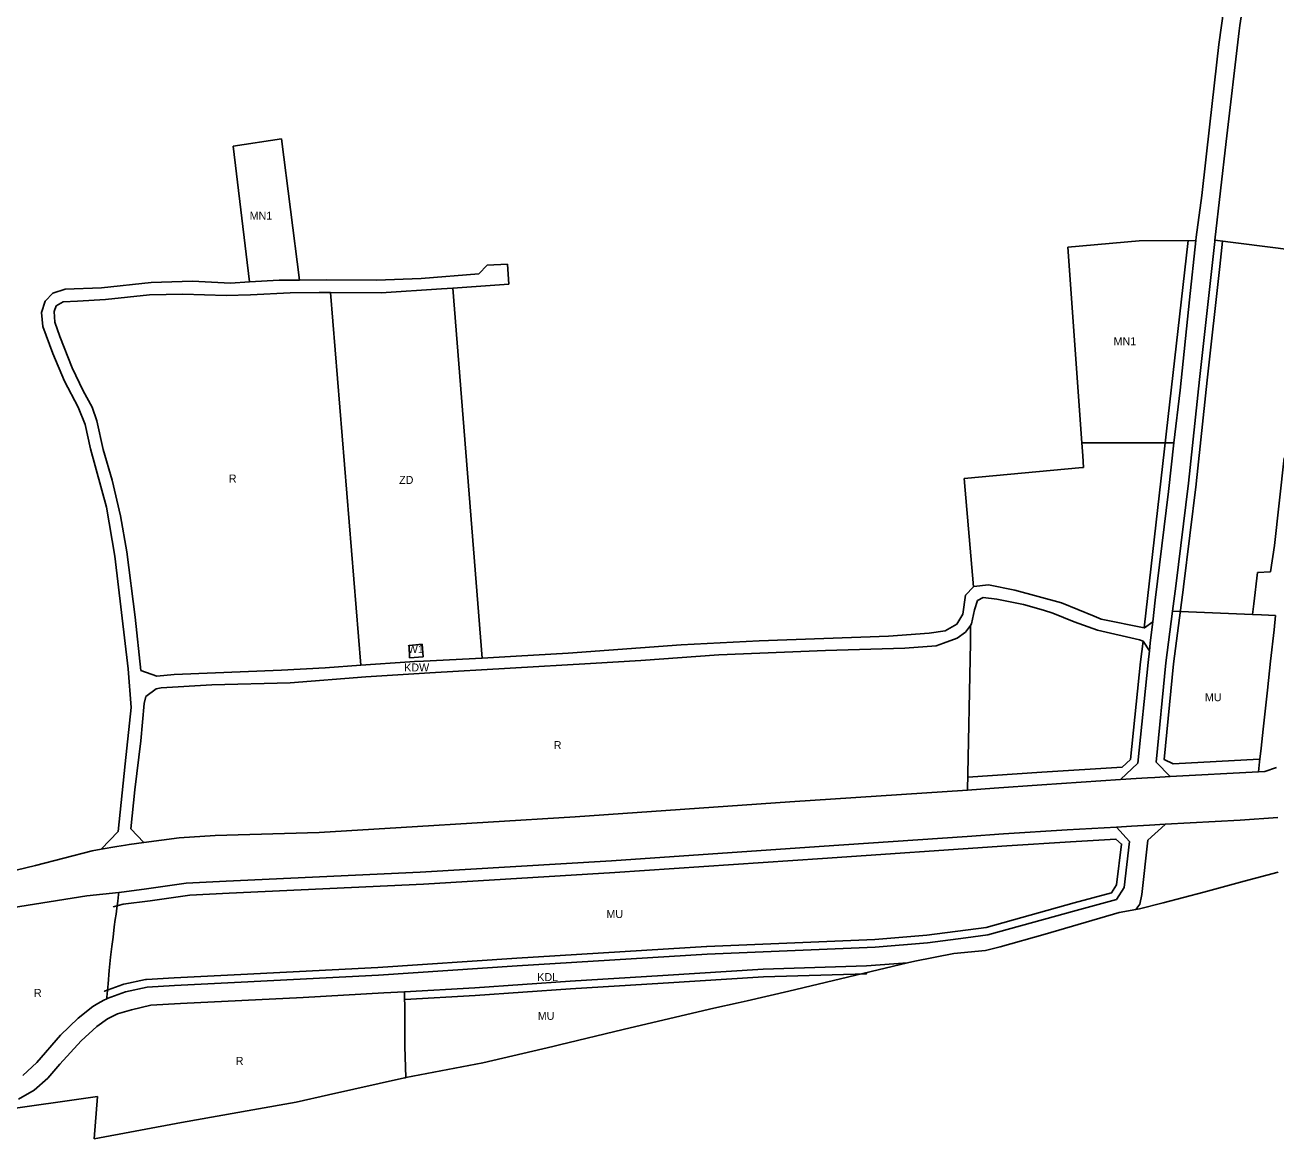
# Model space of a CAD drawing. Extents: x 7435758 to 7439981, y 5550649 to 5554049.
# Drawn here: x 7438238 to 7439051, y 5550993 to 5551717 of the extents above; entities that cross this region are included whole.
import ezdxf

# ---------------------------------------------------------------- set-up
doc = ezdxf.new("R2010")
doc.units = 0
for name, color, linetype in [('linie_rozgraniczające', 7, 'Continuous'), ('linie_zabudowy_nieprzekraczalne', 7, 'Continuous'), ('oznaczenia_przeznaczen', 7, 'Continuous')]:
    doc.layers.add(name, color=color, linetype=linetype)

msp = doc.modelspace()

# ---------------------------------------------------------------- linework, layer by layer
at = {"layer": 'linie_rozgraniczające'}
for p, q in [((7439017.3, 5551727.41), (7439013.95, 5551704.23)), ((7439027.73, 5551716.53), (7439028.84, 5551725.06)), ((7439018.8, 5551641.23), (7439027.27, 5551713.06)), ((7439027.27, 5551713.06), (7439027.73, 5551716.53)), ((7439013.95, 5551704.23), (7439008.23, 5551652.42)), ((7439008.23, 5551652.42), (7439002.96, 5551605.98)), ((7438404.98, 5551642.99), (7438373.55, 5551638.09)), ((7438416.69, 5551551.17), (7438404.98, 5551642.99)), ((7439011.46, 5551576.97), (7439018.8, 5551641.23)), ((7438373.55, 5551638.09), (7438384.24, 5551549.91)), ((7439002.96, 5551605.98), (7438999.36, 5551579)), ((7438962.26, 5551576.72), (7438915.92, 5551572.56)), ((7438999.12, 5551576.76), (7438962.26, 5551576.72)), ((7438999.12, 5551576.76), (7438994.89, 5551538.32)), ((7438999.36, 5551579), (7438999.12, 5551576.76)), ((7439009.58, 5551560.59), (7439011.37, 5551576.2)), ((7439011.37, 5551576.2), (7439011.46, 5551576.97)), ((7439060.87, 5551570.69), (7439011.46, 5551576.97)), ((7438915.92, 5551572.56), (7438924.98, 5551445.38)), ((7438538.69, 5551560.87), (7438533.17, 5551555.11)), ((7438551.9, 5551561.56), (7438538.69, 5551560.87)), ((7438552.77, 5551548.57), (7438551.9, 5551561.56)), ((7439001.47, 5551486.59), (7439009.58, 5551560.59)), ((7438320.35, 5551549.63), (7438288.03, 5551546.08)), ((7438347.18, 5551550.35), (7438320.35, 5551549.63)), ((7438371.85, 5551549.11), (7438347.18, 5551550.35)), ((7438384.24, 5551549.91), (7438371.85, 5551549.11)), ((7438403.56, 5551551.14), (7438384.24, 5551549.91)), ((7438416.69, 5551551.17), (7438403.56, 5551551.14)), ((7438434.3, 5551551.2), (7438416.69, 5551551.17)), ((7438466.84, 5551551.03), (7438434.3, 5551551.2)), ((7438495.74, 5551552.2), (7438466.84, 5551551.03)), ((7438533.17, 5551555.11), (7438495.74, 5551552.2)), ((7438256.46, 5551542.56), (7438251.44, 5551537.51)), ((7438264.56, 5551545.13), (7438256.46, 5551542.56)), ((7438288.03, 5551546.08), (7438264.56, 5551545.13)), ((7438290.65, 5551538.5), (7438319.18, 5551541.45)), ((7438319.18, 5551541.45), (7438340.95, 5551542.04)), ((7438340.95, 5551542.04), (7438369.04, 5551541.09)), ((7438369.04, 5551541.09), (7438384.99, 5551541.59)), ((7438384.99, 5551541.59), (7438410.61, 5551542.92)), ((7438410.61, 5551542.92), (7438429.4, 5551543.09)), ((7438429.4, 5551543.09), (7438436.88, 5551543.06)), ((7438436.88, 5551543.06), (7438456.5, 5551300.82)), ((7438436.88, 5551543.06), (7438469.7, 5551542.93)), ((7438469.7, 5551542.93), (7438509, 5551545.42)), ((7438509, 5551545.42), (7438516.39, 5551545.95)), ((7438516.39, 5551545.95), (7438552.77, 5551548.57)), ((7438535.38, 5551305.53), (7438516.39, 5551545.95)), ((7438251.44, 5551537.51), (7438249.14, 5551529.96)), ((7438257.39, 5551530.74), (7438258.73, 5551534.37)), ((7438258.73, 5551534.37), (7438263.11, 5551536.94)), ((7438263.11, 5551536.94), (7438272.49, 5551537.47)), ((7438272.49, 5551537.47), (7438290.65, 5551538.5)), ((7438994.89, 5551538.32), (7438988.81, 5551479.6)), ((7438249.14, 5551529.96), (7438249.87, 5551521.03)), ((7438257.67, 5551523.88), (7438257.39, 5551530.74)), ((7438249.87, 5551521.03), (7438256.56, 5551503.39)), ((7438261.03, 5551514.47), (7438257.67, 5551523.88)), ((7438269.02, 5551494.2), (7438261.03, 5551514.47)), ((7438256.56, 5551503.39), (7438264, 5551485.41)), ((7438276.19, 5551479.27), (7438269.02, 5551494.2)), ((7438264, 5551485.41), (7438272.89, 5551468.61)), ((7438994.19, 5551419.2), (7439001.47, 5551486.59)), ((7438282, 5551468.46), (7438276.19, 5551479.27)), ((7438988.81, 5551479.6), (7438984.84, 5551445.28)), ((7438272.89, 5551468.61), (7438277.46, 5551457.23)), ((7438285.05, 5551459.63), (7438282, 5551468.46)), ((7438289.23, 5551441.15), (7438285.05, 5551459.63)), ((7438277.46, 5551457.23), (7438280.89, 5551441.52)), ((7438924.98, 5551445.38), (7438925.58, 5551436.89)), ((7438984.84, 5551445.28), (7438924.98, 5551445.38)), ((7438984.84, 5551445.28), (7438981.19, 5551413.78)), ((7438280.89, 5551441.52), (7438291.39, 5551403.51)), ((7438295.12, 5551421.09), (7438289.23, 5551441.15)), ((7438925.58, 5551436.89), (7438926.11, 5551429.43)), ((7439050.2, 5551378.72), (7439056.33, 5551435.64)), ((7438925.49, 5551429.38), (7438848.64, 5551422.1)), ((7438926.11, 5551429.43), (7438925.49, 5551429.38)), ((7438300.53, 5551398.03), (7438295.12, 5551421.09)), ((7438848.64, 5551422.1), (7438854.66, 5551351.81)), ((7438986.07, 5551352.33), (7438994.19, 5551419.2)), ((7438981.19, 5551413.78), (7438972.72, 5551343.24)), ((7438291.39, 5551403.51), (7438296.79, 5551371.65)), ((7438304.46, 5551374.61), (7438300.53, 5551398.03)), ((7439047.63, 5551361.46), (7439050.2, 5551378.72)), ((7438296.79, 5551371.65), (7438305.35, 5551298.5)), ((7438309.92, 5551332), (7438304.46, 5551374.61)), ((7439036.63, 5551340.68), (7439039.15, 5551361.12)), ((7439039.15, 5551361.12), (7439047.63, 5551361.46)), ((7438849.42, 5551346.5), (7438847.68, 5551334.12)), ((7438854.66, 5551351.81), (7438849.42, 5551346.5)), ((7438854.79, 5551351.94), (7438854.66, 5551351.81)), ((7438864.45, 5551353.08), (7438854.79, 5551351.94)), ((7438881.38, 5551349.66), (7438864.45, 5551353.08)), ((7438911.75, 5551341.38), (7438881.38, 5551349.66)), ((7438983.94, 5551335.93), (7438986.07, 5551352.33)), ((7438855.22, 5551336.85), (7438857.21, 5551342.9)), ((7438857.21, 5551342.9), (7438860.86, 5551344.91)), ((7438860.86, 5551344.91), (7438869.86, 5551343.79)), ((7438869.86, 5551343.79), (7438887.16, 5551340.38)), ((7438887.16, 5551340.38), (7438900.01, 5551336.59)), ((7438933.03, 5551332.71), (7438911.75, 5551341.38)), ((7438972.72, 5551343.24), (7438971.08, 5551329.11)), ((7439035.78, 5551333.81), (7439036.63, 5551340.68)), ((7438313.71, 5551297.53), (7438309.92, 5551332)), ((7438847.68, 5551334.12), (7438843.84, 5551327.62)), ((7438853.35, 5551327.82), (7438855.22, 5551336.85)), ((7438906.04, 5551334.81), (7438900.01, 5551336.59)), ((7438920.08, 5551329.04), (7438906.04, 5551334.81)), ((7438933.03, 5551332.71), (7438937.54, 5551330.86)), ((7438937.54, 5551330.86), (7438965.52, 5551325.2)), ((7438979.59, 5551302.4), (7438983.94, 5551335.93)), ((7439035.78, 5551333.81), (7438983.94, 5551335.93)), ((7439041.62, 5551333.66), (7439035.78, 5551333.81)), ((7439046.18, 5551333.38), (7439041.62, 5551333.66)), ((7439050.87, 5551333.09), (7439046.18, 5551333.38)), ((7439049.86, 5551323.88), (7439050.87, 5551333.09)), ((7438825.8, 5551321.67), (7438799.39, 5551319.85)), ((7438836.19, 5551323.21), (7438825.8, 5551321.67)), ((7438843.84, 5551327.62), (7438836.19, 5551323.21)), ((7438844.03, 5551318.49), (7438849.46, 5551322.44)), ((7438849.46, 5551322.44), (7438852.56, 5551326.73)), ((7438852.56, 5551326.73), (7438853.35, 5551327.82)), ((7438852.56, 5551326.73), (7438852.61, 5551315.53)), ((7438935.22, 5551323.68), (7438920.08, 5551329.04)), ((7438962.34, 5551317.32), (7438935.22, 5551323.68)), ((7438965.52, 5551325.2), (7438965.64, 5551325.25)), ((7438965.64, 5551325.25), (7438971.08, 5551329.11)), ((7438970.51, 5551324.19), (7438969.46, 5551315.18)), ((7438971.08, 5551329.11), (7438970.51, 5551324.19)), ((7439047.62, 5551303.62), (7439049.86, 5551323.88)), ((7438487.94, 5551313.78), (7438496.46, 5551314.51)), ((7438488.26, 5551305.79), (7438487.94, 5551313.78)), ((7438496.46, 5551314.51), (7438497.06, 5551306.38)), ((7438664.74, 5551314.2), (7438591.28, 5551308.79)), ((7438715.39, 5551316.63), (7438664.74, 5551314.2)), ((7438799.39, 5551319.85), (7438715.39, 5551316.63)), ((7438809.97, 5551311.88), (7438830.43, 5551313.46)), ((7438830.43, 5551313.46), (7438835.09, 5551315.18)), ((7438835.09, 5551315.18), (7438844.03, 5551318.49)), ((7438852.55, 5551315.4), (7438850.71, 5551219.79)), ((7438852.61, 5551315.53), (7438852.55, 5551315.4)), ((7438964.72, 5551316.6), (7438962.34, 5551317.32)), ((7438968.85, 5551310.23), (7438964.72, 5551316.6)), ((7438969.46, 5551315.18), (7438968.88, 5551310.16)), ((7438497.06, 5551306.38), (7438488.26, 5551305.79)), ((7438535.38, 5551305.53), (7438497.27, 5551303.55)), ((7438557.41, 5551306.67), (7438535.38, 5551305.53)), ((7438591.28, 5551308.79), (7438557.41, 5551306.67)), ((7438638.48, 5551303.99), (7438689.08, 5551307.54)), ((7438689.08, 5551307.54), (7438758.54, 5551310.54)), ((7438758.54, 5551310.54), (7438809.97, 5551311.88)), ((7438968.88, 5551310.16), (7438967.99, 5551302.55)), ((7438968.88, 5551310.16), (7438968.85, 5551310.23)), ((7438305.35, 5551298.5), (7438307.46, 5551273.52)), ((7438313.72, 5551297.45), (7438313.71, 5551297.53)), ((7438324.1, 5551293.67), (7438313.72, 5551297.45)), ((7438405, 5551297.69), (7438335.35, 5551294.86)), ((7438433.29, 5551299.21), (7438405, 5551297.69)), ((7438456.5, 5551300.82), (7438433.29, 5551299.21)), ((7438488.37, 5551303.03), (7438456.5, 5551300.82)), ((7438491.52, 5551303.25), (7438488.37, 5551303.03)), ((7438497.27, 5551303.55), (7438491.52, 5551303.25)), ((7438501.32, 5551296), (7438605.74, 5551301.92)), ((7438605.74, 5551301.92), (7438638.48, 5551303.99)), ((7438967.99, 5551302.55), (7438961.32, 5551237.2)), ((7438973.26, 5551237.8), (7438979.59, 5551302.4)), ((7439045.53, 5551284.64), (7439047.62, 5551303.62)), ((7438335.35, 5551294.86), (7438324.1, 5551293.67)), ((7438359.68, 5551288.2), (7438410.74, 5551289.53)), ((7438410.74, 5551289.53), (7438459.83, 5551293.39)), ((7438459.83, 5551293.39), (7438501.32, 5551296)), ((7438316.9, 5551280.59), (7438323.52, 5551285.53)), ((7438323.52, 5551285.53), (7438326.93, 5551286.13)), ((7438326.93, 5551286.13), (7438359.68, 5551288.2)), ((7439042.73, 5551259.23), (7439045.53, 5551284.64)), ((7438307.46, 5551273.52), (7438303.38, 5551236.86)), ((7438313.59, 5551251.82), (7438315.78, 5551275.97)), ((7438315.78, 5551275.97), (7438316.9, 5551280.59)), ((7439041.38, 5551246.96), (7439042.73, 5551259.23)), ((7438309.66, 5551219.95), (7438313.59, 5551251.82)), ((7439040.4, 5551238.14), (7439041.38, 5551246.96)), ((7438303.38, 5551236.86), (7438298.99, 5551192.81)), ((7438961.32, 5551237.2), (7438950.17, 5551226.55)), ((7438982.38, 5551228.55), (7438973.26, 5551237.8)), ((7439039.69, 5551231.7), (7439040.4, 5551238.14)), ((7439043.9, 5551231.93), (7439039.69, 5551231.7)), ((7439051.35, 5551234.41), (7439043.9, 5551231.93)), ((7438950.17, 5551226.55), (7438899.02, 5551223.06)), ((7438950.17, 5551226.55), (7438960.3, 5551227.24)), ((7438960.3, 5551227.24), (7438967.6, 5551227.74)), ((7438967.6, 5551227.74), (7438972.3, 5551228)), ((7438972.3, 5551228), (7438982.38, 5551228.55)), ((7439039.69, 5551231.7), (7438982.38, 5551228.55)), ((7438307.04, 5551194.5), (7438309.66, 5551219.95)), ((7438850.71, 5551219.79), (7438735.34, 5551212.15)), ((7438868, 5551220.94), (7438850.71, 5551219.79)), ((7438899.02, 5551223.06), (7438868, 5551220.94)), ((7438735.34, 5551212.15), (7438595.91, 5551202.43)), ((7438595.91, 5551202.43), (7438482.67, 5551195.4)), ((7438979.16, 5551197.55), (7439027.83, 5551200.3)), ((7439027.83, 5551200.3), (7439052.32, 5551202.01)), ((7438298.99, 5551192.81), (7438287.85, 5551181.29)), ((7438315.64, 5551185.67), (7438307.04, 5551194.5)), ((7438429.53, 5551192.27), (7438361.88, 5551190.33)), ((7438482.67, 5551195.4), (7438429.53, 5551192.27)), ((7438850.43, 5551189.67), (7438874.07, 5551191.3)), ((7438874.07, 5551191.3), (7438915.54, 5551193.96)), ((7438915.54, 5551193.96), (7438947.41, 5551195.76)), ((7438957.27, 5551196.32), (7438947.41, 5551195.76)), ((7438947.41, 5551195.76), (7438955.93, 5551186.41)), ((7438969.02, 5551196.98), (7438957.27, 5551196.32)), ((7438967.95, 5551187.31), (7438979.01, 5551197.39)), ((7438979.16, 5551197.55), (7438969.02, 5551196.98)), ((7438979.01, 5551197.39), (7438979.16, 5551197.55)), ((7438303.67, 5551184.07), (7438297.95, 5551183.07)), ((7438306, 5551184.38), (7438303.67, 5551184.07)), ((7438315.64, 5551185.67), (7438306, 5551184.38)), ((7438338.56, 5551188.74), (7438315.64, 5551185.67)), ((7438361.88, 5551190.33), (7438338.56, 5551188.74)), ((7438754.39, 5551183.04), (7438850.43, 5551189.67)), ((7438956.05, 5551186.35), (7438952.39, 5551156.54)), ((7438955.93, 5551186.41), (7438956.05, 5551186.35)), ((7438964.02, 5551151.95), (7438967.95, 5551187.31)), ((7438282.06, 5551180.27), (7438245.26, 5551170.82)), ((7438287.85, 5551181.29), (7438282.06, 5551180.27)), ((7438297.95, 5551183.07), (7438287.85, 5551181.29)), ((7438619.48, 5551173.83), (7438754.39, 5551183.04)), ((7438245.26, 5551170.82), (7438218.29, 5551164.39)), ((7438495.22, 5551166.35), (7438619.48, 5551173.83)), ((7438317.33, 5551155.56), (7438343.17, 5551159.2)), ((7438343.17, 5551159.2), (7438369.1, 5551160.58)), ((7438369.1, 5551160.58), (7438495.22, 5551166.35)), ((7439030.35, 5551160.62), (7439004.13, 5551153.45)), ((7439052.63, 5551166.35), (7439030.35, 5551160.62)), ((7438219.56, 5551141.68), (7438278.56, 5551151.11)), ((7438278.56, 5551151.11), (7438299.39, 5551153.17)), ((7438299.23, 5551151.96), (7438298.67, 5551147.65)), ((7438299.39, 5551153.17), (7438299.23, 5551151.96)), ((7438299.39, 5551153.17), (7438299.56, 5551153.21)), ((7438299.56, 5551153.21), (7438317.33, 5551155.56)), ((7438952.39, 5551156.54), (7438947.58, 5551148.65)), ((7438962.6, 5551145.73), (7438964.02, 5551151.95)), ((7439004.13, 5551153.45), (7438977.77, 5551146.59)), ((7438298.06, 5551143), (7438297.81, 5551141.07)), ((7438298.67, 5551147.65), (7438298.06, 5551143)), ((7438947.58, 5551148.65), (7438921.37, 5551141.6)), ((7438960.11, 5551142.17), (7438962.6, 5551145.73)), ((7438962.48, 5551142.62), (7438960.11, 5551142.17)), ((7438977.77, 5551146.59), (7438962.48, 5551142.62)), ((7438297.05, 5551135.62), (7438296.4, 5551130.95)), ((7438297.54, 5551139.03), (7438297.05, 5551135.62)), ((7438297.81, 5551141.07), (7438297.54, 5551139.03)), ((7438921.37, 5551141.6), (7438863.9, 5551125.6)), ((7438949.34, 5551140.13), (7438901.06, 5551126.16)), ((7438960.11, 5551142.17), (7438949.34, 5551140.13)), ((7438296.4, 5551130.95), (7438295.57, 5551124.22)), ((7438294.84, 5551118.2), (7438293.97, 5551111.11)), ((7438295.57, 5551124.22), (7438294.84, 5551118.2)), ((7438824.79, 5551120.59), (7438790.72, 5551117.67)), ((7438849.53, 5551123.76), (7438824.79, 5551120.59)), ((7438863.9, 5551125.6), (7438849.53, 5551123.76)), ((7438901.06, 5551126.16), (7438871.92, 5551117.84)), ((7438293.97, 5551111.11), (7438293.05, 5551102.61)), ((7438681.49, 5551113.24), (7438558.17, 5551105.5)), ((7438790.72, 5551117.67), (7438681.49, 5551113.24)), ((7438841.9, 5551113.64), (7438816.43, 5551108.51)), ((7438862.3, 5551115.55), (7438841.9, 5551113.64)), ((7438871.92, 5551117.84), (7438862.3, 5551115.55)), ((7438293.05, 5551102.61), (7438292.33, 5551093.97)), ((7438558.17, 5551105.5), (7438467.96, 5551099.54)), ((7438652.75, 5551099.27), (7438717.85, 5551103.31)), ((7438717.85, 5551103.31), (7438784.98, 5551105.47)), ((7438811.82, 5551107.42), (7438734.59, 5551089.21)), ((7438784.98, 5551105.47), (7438811.82, 5551107.42)), ((7438816.43, 5551108.51), (7438811.82, 5551107.42)), ((7438292.33, 5551093.97), (7438291.77, 5551087.32)), ((7438378.87, 5551094.87), (7438335.55, 5551092.77)), ((7438467.96, 5551099.54), (7438378.87, 5551094.87)), ((7438530.54, 5551091.37), (7438592.55, 5551095.56)), ((7438592.55, 5551095.56), (7438652.75, 5551099.27)), ((7438291.77, 5551087.32), (7438291.6, 5551085.29)), ((7438303.64, 5551088.74), (7438291.77, 5551084.34)), ((7438317.73, 5551091.69), (7438303.64, 5551088.74)), ((7438335.55, 5551092.77), (7438317.73, 5551091.69)), ((7438419.18, 5551085.03), (7438471.44, 5551087.99)), ((7438471.44, 5551087.99), (7438485.03, 5551088.76)), ((7438485.03, 5551088.76), (7438530.54, 5551091.37)), ((7438485.03, 5551088.76), (7438485.1, 5551075.37)), ((7438734.59, 5551089.21), (7438707.57, 5551082.84)), ((7438282.46, 5551079.2), (7438272.97, 5551071.53)), ((7438285.81, 5551081.05), (7438282.46, 5551079.2)), ((7438289.63, 5551083.15), (7438285.81, 5551081.05)), ((7438291.51, 5551084.19), (7438289.63, 5551083.15)), ((7438291.6, 5551085.29), (7438291.51, 5551084.19)), ((7438291.77, 5551084.34), (7438291.51, 5551084.19)), ((7438307.62, 5551077), (7438320.1, 5551080.03)), ((7438320.1, 5551080.03), (7438339.38, 5551081.09)), ((7438339.38, 5551081.09), (7438419.18, 5551085.03)), ((7438685.83, 5551078.06), (7438635.17, 5551066.25)), ((7438701.66, 5551081.54), (7438685.83, 5551078.06)), ((7438707.57, 5551082.84), (7438701.66, 5551081.54)), ((7438272.97, 5551071.53), (7438261.38, 5551060.42)), ((7438284.95, 5551066.14), (7438292.03, 5551071.19)), ((7438292.03, 5551071.19), (7438298.48, 5551074.39)), ((7438298.48, 5551074.39), (7438307.62, 5551077)), ((7438485.1, 5551075.37), (7438485.23, 5551053.06)), ((7438274.97, 5551056.77), (7438284.95, 5551066.14)), ((7438627.04, 5551064.27), (7438585.63, 5551054.18)), ((7438635.17, 5551066.25), (7438627.04, 5551064.27)), ((7438261.38, 5551060.42), (7438246.13, 5551042.72)), ((7438261.02, 5551041.64), (7438274.97, 5551056.77)), ((7438581.26, 5551053.17), (7438535.86, 5551042.59)), ((7438585.63, 5551054.18), (7438581.26, 5551053.17)), ((7438485.23, 5551053.06), (7438485.91, 5551033.02)), ((7438246.13, 5551042.72), (7438236.95, 5551034.22)), ((7438253.26, 5551032.64), (7438261.02, 5551041.64)), ((7438535.86, 5551042.59), (7438485.91, 5551033.02)), ((7438244.34, 5551024.72), (7438253.26, 5551032.64)), ((7438484.93, 5551032.72), (7438435.63, 5551021.78)), ((7438485.35, 5551032.85), (7438484.93, 5551032.72)), ((7438485.91, 5551033.02), (7438485.35, 5551032.85)), ((7438285.51, 5551020.71), (7438217.88, 5551011.01)), ((7438234.21, 5551018.98), (7438244.34, 5551024.72)), ((7438283.23, 5550993.06), (7438285.51, 5551020.71)), ((7438435.63, 5551021.78), (7438414.57, 5551016.97)), ((7438414.57, 5551016.97), (7438386.39, 5551011.97)), ((7438363.24, 5551007.9), (7438340.08, 5551003.84)), ((7438386.39, 5551011.97), (7438363.24, 5551007.9)), ((7438340.08, 5551003.84), (7438283.23, 5550993.06))]:
    msp.add_line(p, q, dxfattribs=at)
at = {"layer": 'linie_zabudowy_nieprzekraczalne'}
for points in [[(7438965.52, 5551325.2), (7438994.05, 5551576.76)], [(7439016.42, 5551576.34), (7439014.55, 5551560.04), (7439006.44, 5551486.04), (7438999.16, 5551418.66), (7438999.16, 5551418.6), (7438991.03, 5551351.72), (7438991.02, 5551351.68), (7438984.55, 5551301.83), (7438978.46, 5551239.64), (7438984.23, 5551236.79), (7439040.16, 5551239.87)], [(7438850.87, 5551228.05), (7438899.09, 5551231.31), (7438951.29, 5551234.7), (7438956.53, 5551239.54), (7438963.02, 5551303.06), (7438963.03, 5551303.13), (7438964.72, 5551316.6)], [(7438289.81, 5551088.93), (7438289.98, 5551089), (7438290.04, 5551089.03), (7438301.9, 5551093.43), (7438302.15, 5551093.51), (7438302.47, 5551093.6), (7438302.61, 5551093.63), (7438316.71, 5551096.59), (7438316.88, 5551096.62), (7438317.21, 5551096.67), (7438317.43, 5551096.68), (7438335.24, 5551097.76), (7438335.3, 5551097.76), (7438378.62, 5551099.87), (7438467.67, 5551104.53), (7438557.84, 5551110.49), (7438557.86, 5551110.49), (7438681.18, 5551118.23), (7438681.29, 5551118.23), (7438790.4, 5551122.66), (7438824.25, 5551125.56), (7438862.91, 5551130.51), (7438920.03, 5551146.42), (7438920.07, 5551146.43), (7438944.36, 5551152.96), (7438947.56, 5551158.22), (7438950.8, 5551184.62), (7438947.07, 5551187.9), (7438917.58, 5551186.24), (7438876.16, 5551183.58), (7438756.48, 5551175.32), (7438756.48, 5551175.32), (7438621.57, 5551166.11), (7438621.53, 5551166.1), (7438497.27, 5551158.63), (7438497.19, 5551158.62), (7438371.1, 5551152.86), (7438345.4, 5551151.49), (7438319.78, 5551147.88), (7438319.74, 5551147.87), (7438302.24, 5551145.56), (7438295.63, 5551143.94)], [(7438785.26, 5551100.48), (7438785.18, 5551100.48), (7438785.14, 5551100.47), (7438718.08, 5551098.31), (7438653.06, 5551094.28), (7438653.06, 5551094.28), (7438592.87, 5551090.57), (7438530.88, 5551086.38), (7438530.82, 5551086.37), (7438485.07, 5551083.76)]]:
    msp.add_lwpolyline(points, dxfattribs=at)

# ---------------------------------------------------------------- texts
at = {"layer": 'oznaczenia_przeznaczen'}
for s, p in [('MN1', (7438384.36, 5551590.36)), ('MN1', (7438945.6, 5551508.78)), ('R', (7438370.81, 5551419.57)), ('ZD', (7438481.45, 5551418.67)), ('W1', (7438487.05, 5551308.74)), ('KDW', (7438484.75, 5551296.82)), ('MU', (7439004.96, 5551277.5)), ('R', (7438581.92, 5551246.36)), ('MU', (7438616.12, 5551136.62)), ('KDL', (7438571.2, 5551095.66)), ('R', (7438244.2, 5551085.34)), ('MU', (7438571.51, 5551070.47)), ('R', (7438375.27, 5551041.22))]:
    msp.add_text(s, height=5.2, dxfattribs=at).set_placement(p)

doc.saveas('drawing.dxf')
